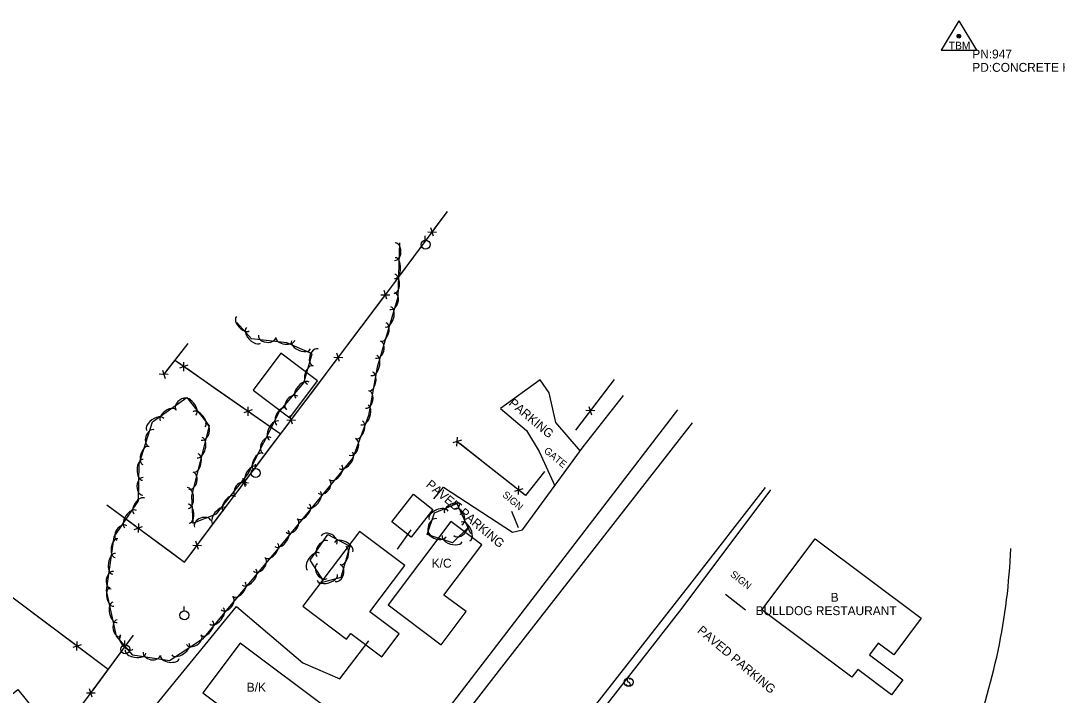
# Model space of a CAD drawing. Extents: x 1441650 to 1491889, y 345904 to 358319.
# Drawn here: x 1442368 to 1442950, y 357940 to 358319 of the extents above; entities that cross this region are included whole.
import ezdxf

# ---------------------------------------------------------------- set-up
doc = ezdxf.new("R2010")
doc.units = 0
for name, color, linetype in [('S_BUILDING', 7, 'Continuous'), ('S_BUILDING_ANNOT', 7, 'Continuous'), ('S_EDGE_PAVEMENT', 7, 'Continuous'), ('S_FENCE', 7, 'Continuous'), ('S_GATE_ANNOT', 7, 'Continuous'), ('S_PARKING', 7, 'Continuous'), ('S_PARKING_ANNOT', 7, 'Continuous'), ('S_PRIMARY_CTL', 7, 'Continuous'), ('S_PRIMARY_CTL_ANNOT', 7, 'Continuous'), ('S_SHOULDER', 7, 'Continuous'), ('S_SIGN', 7, 'Continuous'), ('S_SIGN_ANNOT', 7, 'Continuous'), ('S_TREE', 7, 'Continuous'), ('S_UTILITY_POLE', 7, 'Continuous')]:
    doc.layers.add(name, color=color, linetype=linetype)

msp = doc.modelspace()

# ---------------------------------------------------------------- linework, layer by layer
at = {"layer": 'S_BUILDING'}
for points in [[(1442498.52, 358111.49), (1442519.04, 358096.04), (1442534.64, 358116.76), (1442514.12, 358132.2)], [(1442576.37, 358037.59), (1442588.57, 358053.05), (1442599.44, 358044.47), (1442587.25, 358029.01)], [(1442609.5, 358037.74), (1442574.25, 357991), (1442604.03, 357968.55), (1442618.03, 357987.12), (1442605.65, 357996.46), (1442626.89, 358024.63)], [(1442558.29, 358032.21), (1442526.48, 357990.21), (1442550.99, 357971.65), (1442553.45, 357974.9), (1442570.73, 357961.82), (1442580.43, 357974.63), (1442564.05, 357987.03), (1442583.69, 358012.97)], [(1442834.68, 357950.38), (1442784.17, 357988.17), (1442813.99, 358028.03), (1442873.57, 357983.46), (1442858.19, 357962.91), (1442849.43, 357969.46), (1442844.45, 357962.8), (1442863.18, 357948.79), (1442856.92, 357940.42), (1442837.89, 357954.66)], [(1442470.28, 357941.55), (1442521.71, 357902.92), (1442542.7, 357930.86), (1442491.27, 357969.49)], [(1442359.08, 357890), (1442333.64, 357921.81), (1442354.96, 357938.87), (1442357.26, 357935.99), (1442366.51, 357943.39), (1442385.87, 357919.18), (1442376.37, 357911.59), (1442380.15, 357906.85)]]:
    msp.add_lwpolyline(points, close=True, dxfattribs=at)
at = {"layer": 'S_EDGE_PAVEMENT'}
for points in [[(1442744.95, 358093.25), (1442639.31, 357957.65), (1442556.55, 357850.95), (1442497.42, 357773.2), (1442437.03, 357692.51), (1442415.08, 357662.72)], [(1442469.94, 357642.8), (1442547.41, 357747.3), (1442605.33, 357824.47), (1442676.7, 357916.69), (1442743.66, 358002.18), (1442786.2, 358056.89)]]:
    msp.add_lwpolyline(points, dxfattribs=at)
at = {"layer": 'S_FENCE'}
for p, q in [((1442599.81, 358197.92), (1442598.23, 358202.67)), ((1442596.52, 358200.37), (1442601.52, 358200.22)), ((1442570.25, 358165.13), (1442575.25, 358164.96)), ((1442573.53, 358162.67), (1442571.98, 358167.42)), ((1442459.6, 358122.24), (1442459.59, 358127.24)), ((1442543.8, 358130), (1442548.8, 358129.82)), ((1442547.08, 358127.53), (1442545.53, 358132.29)), ((1442447.61, 358122.8), (1442449.05, 358118.01)), ((1442461.94, 358125.6), (1442457.25, 358123.88)), ((1442450.83, 358120.27), (1442445.83, 358120.54)), ((1442497.99, 358100.42), (1442493.29, 358098.7)), ((1442495.64, 358097.06), (1442495.64, 358102.06)), ((1442690.25, 358099.89), (1442685.26, 358100.1)), ((1442687, 358102.38), (1442688.51, 358097.61)), ((1442517.35, 358094.86), (1442522.35, 358094.7)), ((1442520.63, 358092.4), (1442519.07, 358097.15)), ((1442615.48, 358083.34), (1442610.69, 358081.93)), ((1442612.94, 358080.15), (1442613.23, 358085.12)), ((1442490.97, 358059.65), (1442495.96, 358059.49)), ((1442494.24, 358057.2), (1442492.69, 358061.95)), ((1442647.44, 358052.9), (1442647.73, 358057.87)), ((1442649.98, 358056.09), (1442645.19, 358054.68)), ((1442431.73, 358033.33), (1442436.47, 358034.92)), ((1442434.17, 358036.62), (1442434.04, 358031.62)), ((1442464.58, 358024.45), (1442469.58, 358024.29)), ((1442467.86, 358021.99), (1442466.3, 358026.74)), ((1442399.51, 357965.3), (1442399.67, 357970.3)), ((1442401.97, 357968.57), (1442397.21, 357967.02)), ((1442405.01, 357941.51), (1442409.87, 357941.48)), ((1442408.17, 357939.17), (1442406.72, 357943.82))]:
    msp.add_line(p, q, dxfattribs=at)
for points in [[(1442416.41, 358047.2), (1442460.02, 358014.95), (1442520.67, 358095.87), (1442574.64, 358167.55), (1442607.68, 358211.93)], [(1442600.21, 358201.9), (1442607.68, 358211.93)], [(1442585.89, 358182.66), (1442597.83, 358198.69)], [(1442573.95, 358166.64), (1442574.64, 358167.55), (1442585.89, 358182.66)], [(1442559.53, 358147.48), (1442571.55, 358163.45)], [(1442547.5, 358131.51), (1442559.53, 358147.48)], [(1442461.93, 358137.7), (1442448, 358119.98)], [(1442461.93, 358137.7), (1442449.57, 358121.98)], [(1442457.96, 358125.89), (1442454.42, 358128.36)], [(1442513.66, 358086.97), (1442454.42, 358128.36)], [(1442533.08, 358112.35), (1442545.1, 358128.31)], [(1442477.62, 358112.15), (1442461.23, 358123.6)], [(1442701.11, 358117.48), (1442679.43, 358089.1)], [(1442701.11, 358117.48), (1442688.97, 358101.58)], [(1442494, 358100.71), (1442477.62, 358112.15)], [(1442521.05, 358096.38), (1442533.08, 358112.35)], [(1442513.66, 358086.97), (1442497.28, 358098.42)], [(1442686.54, 358098.4), (1442679.43, 358089.1)], [(1442506.66, 358077.18), (1442518.65, 358093.18)], [(1442662.09, 358065.75), (1442651.35, 358052.41), (1442612.93, 358082.76)], [(1442630.34, 358069.01), (1442614.66, 358081.4)], [(1442494.66, 358061.17), (1442506.66, 358077.18)], [(1442646.01, 358056.62), (1442630.34, 358069.01)], [(1442662.09, 358065.75), (1442651.35, 358052.41), (1442649.15, 358054.15)], [(1442480.27, 358041.97), (1442492.27, 358057.97)], [(1442416.41, 358047.2), (1442432.49, 358035.31)], [(1442468.28, 358025.97), (1442480.27, 358041.97)], [(1442435.71, 358032.93), (1442451.79, 358021.04)], [(1442451.79, 358021.04), (1442460.02, 358014.95), (1442465.88, 358022.77)], [(1442417.18, 357954.58), (1442362.96, 357995.34)], [(1442382, 357981.02), (1442366.02, 357993.04)], [(1442397.99, 357969), (1442382, 357981.02)], [(1442368.81, 357887.99), (1442377.68, 357901.11), (1442431.39, 357973.98)], [(1442420.5, 357959.2), (1442431.39, 357973.98)], [(1442417.18, 357954.58), (1442401.19, 357966.59)], [(1442408.63, 357943.1), (1442420.5, 357959.2)]]:
    msp.add_lwpolyline(points, dxfattribs=at)
at = {"layer": 'S_PARKING'}
for points in [[(1442682.29, 358077.19), (1442668.45, 358093.33), (1442664.69, 358109.98), (1442659.63, 358117.26), (1442637.46, 358101.13), (1442652.06, 358088.84), (1442659.17, 358077.05), (1442667.91, 358057.69)], [(1442599.99, 358050.44), (1442605.46, 358056.94), (1442644.16, 358031.84), (1442649.67, 358033.07), (1442683.73, 358079.71), (1442706.49, 358108.6)], [(1442579.54, 358022.18), (1442587.21, 358032.99)], [(1442446.48, 357852.16), (1442479.67, 357903.76), (1442442.27, 357932.51), (1442489.26, 357990.03), (1442526.49, 357958.3), (1442547.17, 357949.42), (1442563.5, 357970.64)]]:
    msp.add_lwpolyline(points, dxfattribs=at)
msp.add_ellipse((1442578.72, 358035.8), major_axis=(249, 239.6), ratio=0.998904, start_param=5.142639, end_param=5.478423, dxfattribs=at)
at = {"layer": 'S_PRIMARY_CTL'}
for p, q in [((1442894.71, 358319), (1442884.67, 358302.48)), ((1442894.71, 358319), (1442904.53, 358302.48)), ((1442884.67, 358302.48), (1442904.53, 358302.48))]:
    msp.add_line(p, q, dxfattribs=at)
for radius in [1.04, 0.609, 0.344]:
    msp.add_circle((1442894.71, 358310.3), radius, dxfattribs=at)
at = {"layer": 'S_SHOULDER'}
for points in [[(1442736.83, 358100.47), (1442591.1, 357910.86), (1442408.21, 357664.32)], [(1442466.5, 357630.89), (1442569.16, 357770.79), (1442739.43, 357989.15), (1442789.1, 358055.6)]]:
    msp.add_lwpolyline(points, dxfattribs=at)
at = {"layer": 'S_SIGN'}
for p, q in [((1442643.61, 358043.5), (1442647.23, 358034.41)), ((1442763.69, 357996.9), (1442774.88, 357988.05))]:
    msp.add_line(p, q, dxfattribs=at)
msp.add_circle((1442709.33, 357947.5), 2.49, dxfattribs=at)
for centre, radius, start, end in [((1442710.02, 357948.82), 1.5, 167.11961, 241.98129), ((1442709.41, 357948.76), 0.95, 16.52582, 156.89569), ((1442708.92, 357946.15), 1.4, 358.65289, 73.70634), ((1442709.18, 357946.67), 1.28, 204.64102, 335.35898)]:
    msp.add_arc(centre, radius, start, end, dxfattribs=at)
at = {"layer": 'S_TREE'}
for points in [[(1442580.63, 358194.17), (1442579.7, 358163.76), (1442568.16, 358124.43), (1442563.2, 358097.34), (1442554.5, 358073.59), (1442514.42, 358024.82), (1442487.15, 357992.32), (1442470.09, 357971.68), (1442451.58, 357959.51), (1442431.01, 357962.77), (1442421.75, 357973.42), (1442416.22, 357998.96), (1442420.49, 358029.23), (1442434.1, 358049.33), (1442434.53, 358070.14), (1442441.93, 358093.65), (1442461.22, 358107.47), (1442473.82, 358091.43), (1442463.93, 358052.18), (1442464.73, 358036.87), (1442477.93, 358042.03), (1442495.56, 358064.28), (1442513.31, 358099.49), (1442526.96, 358115.7), (1442531.7, 358131.95), (1442517.47, 358138.05), (1442497.59, 358140.39), (1442489.27, 358149.49)], [(1442619.97, 358035.11), (1442610.45, 358025.86), (1442596.25, 358030.36), (1442600.33, 358042.57), (1442612.82, 358047.93), (1442620.58, 358031.1)], [(1442538.02, 358004.48), (1442530.47, 358016.03), (1442540.4, 358030.43), (1442552.74, 358023.94), (1442547.66, 358006.24), (1442535.12, 358002.85)]]:
    msp.add_lwpolyline(points, dxfattribs=at)
for centre, major_axis, ratio, start_param, end_param in [((1442578.1, 358189.29), (0.15, 4.95), 0.685003, 3.141319, 6.282912), ((1442578.08, 358180.03), (0.18, 5.87), 0.549833, 3.141426, 6.283018), ((1442577.81, 358171.17), (0.16, 5.34), 0.540457, 3.141431, 6.283023), ((1442576.58, 358161.59), (1.4, 4.75), 0.685037, 3.141999, 6.283592), ((1442574.23, 358152.64), (1.65, 5.63), 0.54986, 3.141841, 6.283433), ((1442492.73, 358148.84), (3.61, -3.95), 0.540597, 3.141718, 6.283311), ((1442498.72, 358142.3), (3.96, -4.33), 0.549976, 3.141722, 6.283315), ((1442571.73, 358144.13), (1.51, 5.13), 0.540483, 3.141833, 6.283426), ((1442506.39, 358141.75), (4.91, -0.58), 0.687406, 3.141706, 6.283299), ((1442516.56, 358140.29), (5.29, -0.62), 0.542352, 3.14166, 6.283252), ((1442525.37, 358136.97), (5.39, -2.31), 0.550942, 3.142032, 6.283625), ((1442568.58, 358134.32), (1.4, 4.75), 0.685037, 3.141999, 6.283592), ((1442533.58, 358129.89), (-1.39, -4.76), 0.685017, 3.141871, 6.283464), ((1442566.22, 358125.36), (1.65, 5.63), 0.54986, 3.141841, 6.283433), ((1442530.45, 358120.08), (-1.5, -5.13), 0.540467, 3.141757, 6.28335), ((1442564.54, 358116.43), (0.96, 5.26), 0.54046, 3.141764, 6.283357), ((1442526.21, 358111.51), (-3.78, -4.49), 0.54991, 3.14166, 6.283253), ((1442562.43, 358106.35), (0.89, 4.87), 0.685008, 3.141882, 6.283475), ((1442459.26, 358103.14), (-4.03, -2.89), 0.685179, 3.14168, 6.283273), ((1442462.73, 358102.12), (-3.63, 4.61), 0.549976, 3.141388, 6.282981), ((1442520.44, 358104.26), (-3.19, -3.79), 0.685099, 3.141704, 6.283296), ((1442450.74, 358097.35), (-4.35, -3.11), 0.540595, 3.141644, 6.283237), ((1442468.21, 358095.15), (-3.3, 4.2), 0.540597, 3.141395, 6.282987), ((1442514.28, 358096.7), (-2.41, -4.77), 0.54048, 3.141593, 6.283185), ((1442561.03, 358097.56), (2.02, 5.51), 0.54985, 3.141436, 6.283029), ((1442443.53, 358092.19), (-4.77, -3.42), 0.549974, 3.141646, 6.283239), ((1442470.56, 358088.22), (1.21, 4.8), 0.685123, 3.140834, 6.282427), ((1442510.29, 358088.78), (-2.64, -5.24), 0.549856, 3.141593, 6.283185), ((1442557.98, 358089.24), (1.84, 5.02), 0.540474, 3.141441, 6.283033), ((1442441.56, 358084.53), (-1.49, -4.73), 0.685058, 3.142088, 6.28368), ((1442468.55, 358079.18), (1.43, 5.69), 0.549929, 3.14113, 6.282722), ((1442506.35, 358080.39), (-2.23, -4.43), 0.685032, 3.141593, 6.283185), ((1442554.19, 358079.66), (1.7, 4.65), 0.685025, 3.141336, 6.282929), ((1442438.21, 358074.78), (-1.61, -5.1), 0.5405, 3.141885, 6.283478), ((1442466.38, 358070.59), (1.31, 5.18), 0.540551, 3.141144, 6.282737), ((1442501.48, 358071.31), (-2.41, -4.77), 0.54048, 3.141593, 6.283185), ((1442550.53, 358072.1), (3.72, 4.53), 0.549958, 3.141312, 6.282905), ((1442436.58, 358066.77), (-0.12, -5.87), 0.549848, 3.141837, 6.283429), ((1442497.49, 358063.39), (-2.64, -5.24), 0.549856, 3.141593, 6.283185), ((1442544.9, 358065.25), (3.39, 4.13), 0.54058, 3.141321, 6.282914), ((1442463.61, 358060.66), (1.21, 4.8), 0.685123, 3.140834, 6.282427), ((1442436.65, 358057.51), (-0.1, -4.95), 0.685022, 3.141992, 6.283585), ((1442491.73, 358055.6), (-3.08, -3.88), 0.685086, 3.141593, 6.283185), ((1442538.16, 358057.46), (3.14, 3.83), 0.68516, 3.141133, 6.282726), ((1442434.69, 358046.42), (-3, -4.43), 0.540505, 3.141593, 6.283185), ((1442461.87, 358050.96), (-0.31, 5.86), 0.549825, 3.141555, 6.283147), ((1442485.12, 358047.69), (-3.32, -4.19), 0.540522, 3.141593, 6.283185), ((1442532.48, 358050.14), (3.72, 4.53), 0.549958, 3.141312, 6.282905), ((1442462.34, 358042.11), (-0.28, 5.34), 0.540449, 3.141556, 6.283149), ((1442479.61, 358040.74), (-3.65, -4.6), 0.5499, 3.141593, 6.283185), ((1442526.85, 358043.29), (3.39, 4.13), 0.54058, 3.141321, 6.282914), ((1442610.78, 358044.75), (-4.91, -2.11), 0.540402, 3.141593, 6.283185), ((1442429.72, 358039.08), (-3.29, -4.86), 0.549882, 3.141593, 6.283185), ((1442470.21, 358036.45), (-4.61, -1.81), 0.685248, 3.141593, 6.283185), ((1442600.16, 358034.55), (-1.57, -4.7), 0.684942, 3.141593, 6.283185), ((1442602.63, 358041.25), (-5.39, -2.31), 0.549777, 3.141593, 6.283185), ((1442613.66, 358040.43), (-2.07, 4.5), 0.685633, 3.142178, 6.283771), ((1442424.74, 358031.27), (-2.78, -4.1), 0.685065, 3.141593, 6.283185), ((1442520.11, 358035.5), (3.14, 3.83), 0.68516, 3.141133, 6.282726), ((1442614.76, 358033.37), (3.56, 3.45), 0.685046, 3.14267, 6.284263), ((1442617.77, 358032.13), (-2.45, 5.33), 0.550339, 3.14195, 6.283543), ((1442421.72, 358022.77), (-0.75, -5.29), 0.540445, 3.141642, 6.283235), ((1442514.44, 358028.18), (3.72, 4.53), 0.549958, 3.141312, 6.282905), ((1442541.09, 358027.38), (-4.37, 2.25), 0.689623, 3.128723, 6.270316), ((1442601.75, 358030.85), (5.09, -1.62), 0.540793, 3.141886, 6.283478), ((1442610.2, 358028.17), (5.59, -1.77), 0.550175, 3.141895, 6.283488), ((1442508.78, 358021.39), (3.43, 4.09), 0.541126, 3.14069, 6.282283), ((1442537.46, 358022.46), (-3.03, -4.4), 0.53532, 3.139909, 6.281501), ((1442549.34, 358023.34), (-5.16, 2.68), 0.553566, 3.133782, 6.275375), ((1442549.02, 358018.62), (1.49, 5.12), 0.538622, 3.14836, 6.289953), ((1442420.48, 358013.99), (-0.82, -5.81), 0.549821, 3.141644, 6.283236), ((1442501.96, 358013.68), (3.18, 3.8), 0.685851, 3.140066, 6.281658), ((1442532.42, 358015.16), (-3.33, -4.83), 0.544607, 3.139855, 6.281448), ((1442496.22, 358006.42), (3.77, 4.49), 0.550513, 3.140661, 6.282254), ((1442537.3, 358009.92), (2.71, -4.14), 0.686483, 3.141501, 6.283094), ((1442545.94, 358008.82), (1.4, 4.74), 0.682652, 3.152996, 6.294588), ((1442419.44, 358004.78), (-0.69, -4.91), 0.684989, 3.141676, 6.283269), ((1442540.15, 358006.38), (5.66, 1.54), 0.544393, 3.13977, 6.281363), ((1442419.15, 357995.42), (1.13, -5.23), 0.540466, 3.141627, 6.28322), ((1442490.53, 357999.64), (3.43, 4.09), 0.541126, 3.14069, 6.282283), ((1442483.71, 357991.9), (3.15, 3.82), 0.685356, 3.140689, 6.282281), ((1442421.03, 357986.75), (1.24, -5.74), 0.549842, 3.141629, 6.283221), ((1442478.02, 357984.6), (3.74, 4.52), 0.550116, 3.141041, 6.282633), ((1442423.25, 357977.76), (1.05, -4.84), 0.685014, 3.141651, 6.283244), ((1442472.37, 357977.76), (3.4, 4.12), 0.540735, 3.141058, 6.282651), ((1442427.54, 357970), (3.51, -4.03), 0.540574, 3.141593, 6.283185), ((1442465.31, 357971.38), (4.14, 2.72), 0.685188, 3.141593, 6.283185), ((1442432.47, 357964.69), (5.8, -0.92), 0.550078, 3.141593, 6.283185), ((1442441.65, 357963.5), (4.89, -0.78), 0.685309, 3.141593, 6.283185), ((1442457.71, 357966.08), (4.9, 3.23), 0.549981, 3.141593, 6.283185), ((1442451.78, 357961.62), (5.28, -0.84), 0.540698, 3.141593, 6.283185)]:
    msp.add_ellipse(centre, major_axis=major_axis, ratio=ratio, start_param=start_param, end_param=end_param, dxfattribs=at)
at = {"layer": 'S_UTILITY_POLE'}
for p, q in [((1442595.18, 358195.78), (1442595.18, 358198.27)), ((1442499.77, 358067.48), (1442499.77, 358069.96)), ((1442459.79, 357987.59), (1442459.79, 357990.07)), ((1442426.58, 357968.5), (1442426.58, 357970.98))]:
    msp.add_line(p, q, dxfattribs=at)
for centre in [(1442595.32, 358193.27), (1442499.92, 358064.96), (1442459.94, 357985.07), (1442426.72, 357965.98)]:
    msp.add_circle(centre, 2.5, dxfattribs=at)

# ---------------------------------------------------------------- texts
at = {"layer": 'S_BUILDING_ANNOT'}
for s, height, p in [('K/C', 5, (1442598.76, 358011.83)), ('B', 5, (1442822.74, 357992.67)), ('BULLDOG RESTAURANT', 5.0003, (1442780.6, 357985.17)), ('B/K', 5, (1442494.91, 357942.16))]:
    msp.add_text(s, height=height, dxfattribs=at).set_placement(p)
at = {"layer": 'S_GATE_ANNOT'}
msp.add_text('GATE', height=4, rotation=320.16171, dxfattribs=at).set_placement((1442661.37, 358076.88))
at = {"layer": 'S_PARKING_ANNOT'}
for s, height, p in [('PARKING', 5, (1442641.6, 358103.56)), ('PAVED PARKING', 5.0003, (1442595.18, 358057.78)), ('PAVED PARKING', 5.0003, (1442747.45, 357975.87))]:
    msp.add_text(s, height=height, rotation=319.89768, dxfattribs=at).set_placement(p)
at = {"layer": 'S_PRIMARY_CTL'}
msp.add_text('TBM', height=4.287, rotation=360, dxfattribs=at).set_placement((1442889.05, 358302.91))
at = {"layer": 'S_PRIMARY_CTL_ANNOT'}
for s, p in [('PN:947', (1442902.21, 358297.8)), ('PD:CONCRETE HEADWALL', (1442902.21, 358290.3))]:
    msp.add_text(s, height=5, dxfattribs=at).set_placement(p)
at = {"layer": 'S_SIGN_ANNOT'}
for rotation, p in [(319.89768, (1442638.04, 358052.17)), (321.99293, (1442765.98, 358007.38))]:
    msp.add_text('SIGN', height=4, rotation=rotation, dxfattribs=at).set_placement(p)

doc.saveas('drawing.dxf')
